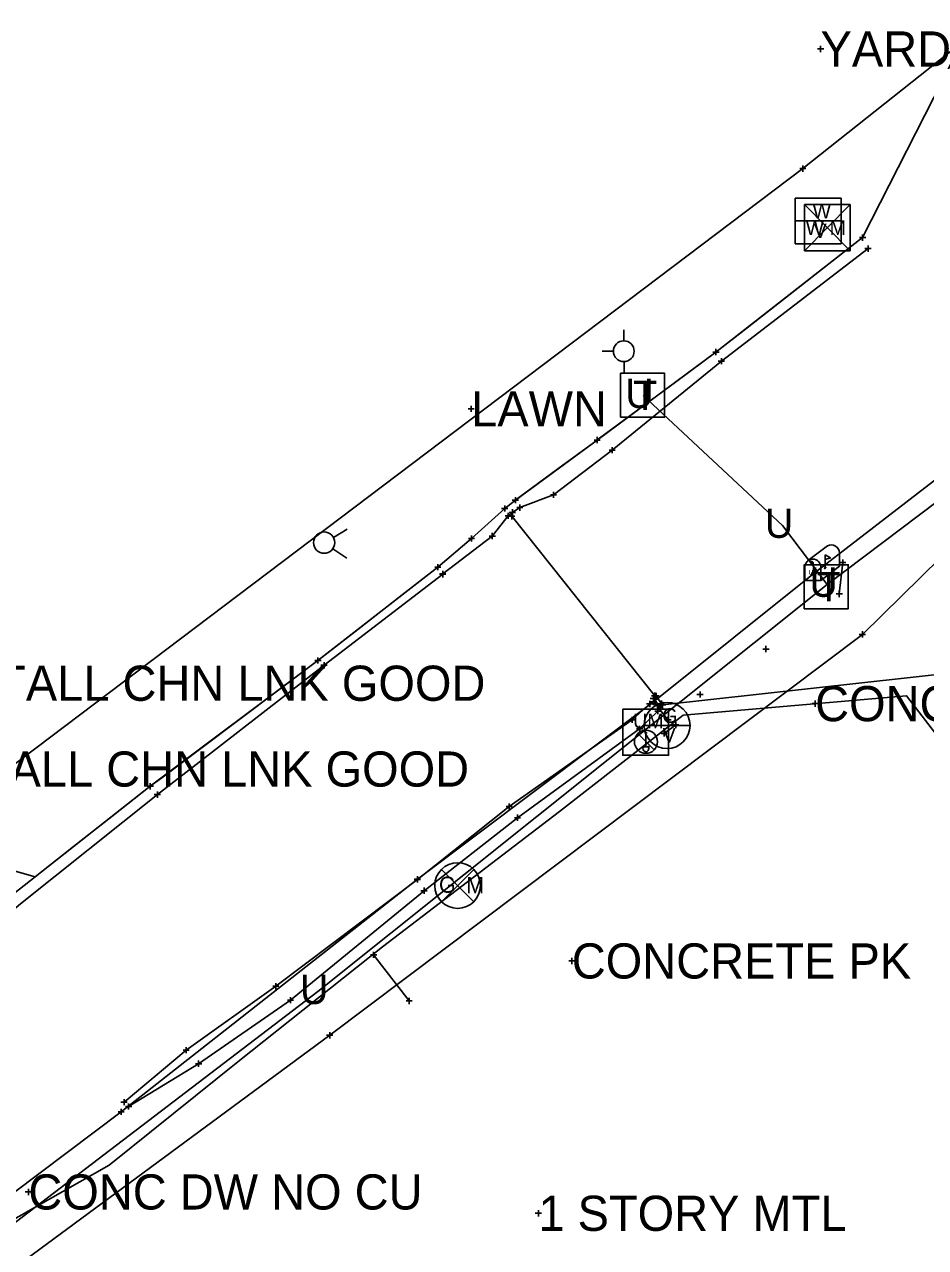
# Model space of a CAD drawing. Extents: x -1 to 1157254, y -1 to 2021979.
# Drawn here: x 1147974.3 to 1148159, y 2017757.2 to 2018007.6 of the extents above; entities that cross this region are included whole.
import ezdxf

# ---------------------------------------------------------------- set-up
doc = ezdxf.new("R2010")
doc.units = 0
for name, color, linetype in [('S_BUILDING_ANNOT', 7, 'Continuous'), ('S_CAL_CORNER', 7, 'Continuous'), ('S_CAL_CORNER_ANNOT', 7, 'Continuous'), ('S_CATCH_BASIN', 7, 'Continuous'), ('S_CATCH_BASIN_ANNOT', 7, 'Continuous'), ('S_CONTOUR_ANNOT', 7, 'Continuous'), ('S_CONTOUR_MAJOR', 7, 'Continuous'), ('S_CROSS_DRAIN', 7, 'Continuous'), ('S_DRIVEWAY_ANNOT', 7, 'Continuous'), ('S_DROP_INLET', 7, 'Continuous'), ('S_DROP_INLET_ANNOT', 7, 'Continuous'), ('S_DTM_PAVEMENT', 7, 'Continuous'), ('S_EXIST_ROW', 7, 'Continuous'), ('S_EXISTING_ALIGNMENT', 7, 'Continuous'), ('S_FENCE', 7, 'Continuous'), ('S_GAS_PUMP_ISLAND_ANNOT', 7, 'Continuous'), ('S_GATE', 7, 'Continuous')]:
    doc.layers.add(name, color=color, linetype=linetype)

msp = doc.modelspace()

# ---------------------------------------------------------------- linework, layer by layer
at = {"layer": 'S_BUILDING_ANNOT'}
for p, q in [((1148136.82, 2018002.62), (1148138.09, 2018002.62)), ((1148137.45, 2018001.99), (1148137.45, 2018003.26)), ((1148137.45, 2018002.62), (1148137.45, 2018002.62)), ((1148133.18, 2017978.12), (1148134.45, 2017978.13)), ((1148133.82, 2017977.49), (1148133.81, 2017978.76)), ((1148133.82, 2017978.13), (1148133.82, 2017978.13)), ((1148146.07, 2017963.35), (1148146.07, 2017964.62)), ((1148145.43, 2017963.99), (1148146.7, 2017963.99)), ((1148146.07, 2017963.99), (1148146.07, 2017963.99)), ((1148147.19, 2017961.09), (1148147.18, 2017962.36)), ((1148146.55, 2017961.73), (1148147.82, 2017961.73)), ((1148147.19, 2017961.73), (1148147.19, 2017961.73)), ((1148115.37, 2017940.55), (1148116.64, 2017940.55)), ((1148116.01, 2017939.91), (1148116, 2017941.19)), ((1148116, 2017940.55), (1148116, 2017940.55)), ((1148116.5, 2017938.7), (1148117.78, 2017938.7)), ((1148117.14, 2017938.06), (1148117.14, 2017939.33)), ((1148117.14, 2017938.7), (1148117.14, 2017938.7)), ((1148065.86, 2017928.3), (1148065.86, 2017929.57)), ((1148065.23, 2017928.93), (1148066.5, 2017928.94)), ((1148065.86, 2017928.93), (1148065.86, 2017928.93)), ((1148091.03, 2017922.54), (1148092.3, 2017922.54)), ((1148091.67, 2017921.9), (1148091.67, 2017923.18)), ((1148091.67, 2017922.54), (1148091.67, 2017922.54)), ((1148094.11, 2017920.47), (1148095.38, 2017920.47)), ((1148094.75, 2017919.83), (1148094.75, 2017921.11)), ((1148094.75, 2017920.47), (1148094.75, 2017920.47)), ((1148082.72, 2017910.68), (1148082.71, 2017911.95)), ((1148074.28, 2017910.22), (1148075.55, 2017910.23)), ((1148074.92, 2017909.59), (1148074.91, 2017910.86)), ((1148074.92, 2017910.22), (1148074.92, 2017910.22)), ((1148075.83, 2017908.07), (1148075.83, 2017909.34)), ((1148082.08, 2017911.31), (1148083.35, 2017911.32)), ((1148082.72, 2017911.31), (1148082.72, 2017911.31)), ((1148072.1, 2017908.52), (1148073.37, 2017908.53)), ((1148072.73, 2017907.89), (1148072.73, 2017909.16)), ((1148072.73, 2017908.52), (1148072.73, 2017908.52)), ((1148072.84, 2017907.01), (1148074.11, 2017907.01)), ((1148073.47, 2017906.37), (1148073.47, 2017907.64)), ((1148073.47, 2017907.01), (1148073.47, 2017907.01)), ((1148073.53, 2017906.94), (1148074.8, 2017906.94)), ((1148073.67, 2017907.71), (1148074.94, 2017907.71)), ((1148074.17, 2017906.3), (1148074.16, 2017907.58)), ((1148074.17, 2017906.94), (1148074.17, 2017906.94)), ((1148074.31, 2017907.07), (1148074.31, 2017908.35)), ((1148074.31, 2017907.71), (1148074.31, 2017907.71)), ((1148075.19, 2017908.7), (1148076.47, 2017908.71)), ((1148075.83, 2017908.7), (1148075.83, 2017908.7)), ((1148065.3, 2017902.36), (1148066.57, 2017902.36)), ((1148065.94, 2017901.73), (1148065.93, 2017903)), ((1148065.94, 2017902.36), (1148065.94, 2017902.36)), ((1148069.55, 2017902.87), (1148070.82, 2017902.87)), ((1148070.19, 2017902.24), (1148070.19, 2017903.51)), ((1148070.19, 2017902.87), (1148070.19, 2017902.87)), ((1148059.01, 2017895.88), (1148059.01, 2017897.15)), ((1148141.36, 2017897.47), (1148142.63, 2017897.47)), ((1148142, 2017896.84), (1148142, 2017898.11)), ((1148142, 2017897.47), (1148142, 2017897.47)), ((1148058.38, 2017896.51), (1148059.65, 2017896.51)), ((1148059.01, 2017896.51), (1148059.01, 2017896.51)), ((1148059.4, 2017895.04), (1148060.67, 2017895.04)), ((1148059.42, 2017895.15), (1148060.69, 2017895.15)), ((1148060.04, 2017894.41), (1148060.03, 2017895.68)), ((1148060.04, 2017895.04), (1148060.04, 2017895.04)), ((1148060.05, 2017894.51), (1148060.05, 2017895.78)), ((1148060.05, 2017895.15), (1148060.05, 2017895.15)), ((1148135.5, 2017895.28), (1148136.77, 2017895.28)), ((1148136.14, 2017894.65), (1148136.13, 2017895.92)), ((1148136.14, 2017895.28), (1148136.14, 2017895.28)), ((1148140.66, 2017891.02), (1148141.93, 2017891.02)), ((1148141.29, 2017890.38), (1148141.29, 2017891.66)), ((1148141.29, 2017891.02), (1148141.29, 2017891.02)), ((1148145.39, 2017882.73), (1148146.67, 2017882.74)), ((1148146.03, 2017882.1), (1148146.03, 2017883.37)), ((1148146.03, 2017882.74), (1148146.03, 2017882.74)), ((1148125.62, 2017879.74), (1148126.9, 2017879.74)), ((1148126.26, 2017879.11), (1148126.26, 2017880.38)), ((1148126.26, 2017879.74), (1148126.26, 2017879.74)), ((1148033.82, 2017877.39), (1148035.09, 2017877.4)), ((1148034.45, 2017876.76), (1148034.45, 2017878.03)), ((1148034.45, 2017877.4), (1148034.45, 2017877.4)), ((1148035.71, 2017875.77), (1148035.71, 2017877.04)), ((1148035.08, 2017876.41), (1148036.35, 2017876.41)), ((1148035.71, 2017876.41), (1148035.71, 2017876.41)), ((1148102.56, 2017869.58), (1148103.83, 2017869.58)), ((1148102.84, 2017870.19), (1148104.12, 2017870.19)), ((1148103.12, 2017870.13), (1148104.4, 2017870.13)), ((1148103.19, 2017868.95), (1148103.19, 2017870.22)), ((1148103.19, 2017869.58), (1148103.19, 2017869.58)), ((1148103.22, 2017868.32), (1148103.22, 2017869.59)), ((1148103.28, 2017868.26), (1148103.28, 2017869.53)), ((1148103.48, 2017869.56), (1148103.48, 2017870.83)), ((1148103.48, 2017870.19), (1148103.48, 2017870.19)), ((1148103.76, 2017869.5), (1148103.76, 2017870.77)), ((1148103.76, 2017870.13), (1148103.76, 2017870.13)), ((1148112.13, 2017870.42), (1148113.4, 2017870.42)), ((1148112.77, 2017869.79), (1148112.76, 2017871.06)), ((1148112.76, 2017870.42), (1148112.76, 2017870.42)), ((1148101.8, 2017868.5), (1148103.07, 2017868.5)), ((1148102.44, 2017867.87), (1148102.44, 2017869.14)), ((1148102.44, 2017868.5), (1148102.44, 2017868.5)), ((1148102.58, 2017868.95), (1148103.85, 2017868.95)), ((1148102.64, 2017868.9), (1148103.91, 2017868.9)), ((1148103.22, 2017868.95), (1148103.22, 2017868.95)), ((1148103.28, 2017868.9), (1148103.28, 2017868.9)), ((1148103.47, 2017867.04), (1148104.75, 2017867.05)), ((1148103.91, 2017867.82), (1148105.19, 2017867.83)), ((1148104.11, 2017866.41), (1148104.11, 2017867.68)), ((1148104.11, 2017867.05), (1148104.11, 2017867.05)), ((1148104.21, 2017868.54), (1148105.48, 2017868.54)), ((1148104.45, 2017868.29), (1148105.73, 2017868.3)), ((1148104.55, 2017867.19), (1148104.55, 2017868.46)), ((1148104.55, 2017867.83), (1148104.55, 2017867.83)), ((1148104.85, 2017867.91), (1148104.84, 2017869.18)), ((1148104.85, 2017868.54), (1148104.85, 2017868.54)), ((1148105.09, 2017867.66), (1148105.09, 2017868.93)), ((1148105.09, 2017868.3), (1148105.09, 2017868.3)), ((1148135.7, 2017868.56), (1148136.97, 2017868.56)), ((1148136.33, 2017867.92), (1148136.33, 2017869.2)), ((1148136.33, 2017868.56), (1148136.33, 2017868.56)), ((1148098.24, 2017865.24), (1148099.51, 2017865.24)), ((1148098.88, 2017864.61), (1148098.87, 2017865.88)), ((1148098.87, 2017865.24), (1148098.87, 2017865.24)), ((1148105.53, 2017865.23), (1148106.81, 2017865.23)), ((1148106.17, 2017864.6), (1148106.17, 2017865.87)), ((1148106.17, 2017865.23), (1148106.17, 2017865.23)), ((1148107.78, 2017863.57), (1148107.78, 2017864.84)), ((1148099.75, 2017863.39), (1148101.02, 2017863.39)), ((1148100.39, 2017862.75), (1148100.38, 2017864.03)), ((1148100.38, 2017863.39), (1148100.38, 2017863.39)), ((1148104.76, 2017862.45), (1148106.03, 2017862.46)), ((1148105.4, 2017861.82), (1148105.4, 2017863.09)), ((1148105.4, 2017862.46), (1148105.4, 2017862.46)), ((1148107.14, 2017864.2), (1148108.41, 2017864.21)), ((1148107.78, 2017864.2), (1148107.78, 2017864.2)), ((1148000.11, 2017851), (1148000.11, 2017852.27)), ((1147999.48, 2017851.64), (1148000.75, 2017851.64)), ((1148000.11, 2017851.64), (1148000.11, 2017851.64)), ((1148000.92, 2017849.93), (1148002.19, 2017849.93)), ((1148001.56, 2017849.29), (1148001.56, 2017850.57)), ((1148001.56, 2017849.93), (1148001.56, 2017849.93)), ((1148073.01, 2017847.51), (1148074.28, 2017847.51)), ((1148073.64, 2017846.87), (1148073.64, 2017848.14)), ((1148073.64, 2017847.51), (1148073.64, 2017847.51)), ((1148074.71, 2017845.2), (1148075.99, 2017845.2)), ((1148075.35, 2017844.56), (1148075.35, 2017845.83)), ((1148075.35, 2017845.2), (1148075.35, 2017845.2)), ((1148054.2, 2017832.57), (1148055.48, 2017832.57)), ((1148054.22, 2017832.59), (1148055.5, 2017832.59)), ((1148054.84, 2017831.93), (1148054.84, 2017833.21)), ((1148054.84, 2017832.57), (1148054.84, 2017832.57)), ((1148054.86, 2017831.96), (1148054.86, 2017833.23)), ((1148054.86, 2017832.59), (1148054.86, 2017832.59)), ((1148055.57, 2017830.24), (1148056.85, 2017830.25)), ((1148056.21, 2017829.61), (1148056.21, 2017830.88)), ((1148056.21, 2017830.24), (1148056.21, 2017830.24)), ((1148045.23, 2017817.12), (1148046.51, 2017817.12)), ((1148045.87, 2017816.49), (1148045.87, 2017817.76)), ((1148045.87, 2017817.12), (1148045.87, 2017817.12)), ((1148085.84, 2017815.87), (1148087.11, 2017815.87)), ((1148086.47, 2017815.23), (1148086.47, 2017816.5)), ((1148086.47, 2017815.87), (1148086.47, 2017815.87)), ((1148025.2, 2017810.69), (1148026.47, 2017810.69)), ((1148025.84, 2017810.05), (1148025.83, 2017811.33)), ((1148025.83, 2017810.69), (1148025.83, 2017810.69)), ((1148028.2, 2017807.84), (1148029.47, 2017807.85)), ((1148028.84, 2017807.21), (1148028.84, 2017808.48)), ((1148028.84, 2017807.85), (1148028.84, 2017807.85)), ((1148052.53, 2017807.69), (1148053.8, 2017807.69)), ((1148053.16, 2017807.05), (1148053.16, 2017808.32)), ((1148053.16, 2017807.69), (1148053.16, 2017807.69)), ((1148036.24, 2017800.65), (1148037.51, 2017800.66)), ((1148036.88, 2017800.02), (1148036.88, 2017801.29)), ((1148036.88, 2017800.65), (1148036.88, 2017800.65)), ((1148006.81, 2017797.6), (1148008.09, 2017797.6)), ((1148007.45, 2017796.96), (1148007.45, 2017798.24)), ((1148007.45, 2017797.6), (1148007.45, 2017797.6)), ((1148009.37, 2017794.82), (1148010.64, 2017794.83)), ((1148010, 2017794.19), (1148010, 2017795.46)), ((1148010, 2017794.83), (1148010, 2017794.83)), ((1147994.08, 2017786.96), (1147995.35, 2017786.97)), ((1147994.72, 2017786.33), (1147994.72, 2017787.6)), ((1147994.72, 2017786.97), (1147994.72, 2017786.97)), ((1147995.66, 2017785.42), (1147995.65, 2017786.7)), ((1147993.5, 2017784.96), (1147994.77, 2017784.97)), ((1147994.13, 2017784.33), (1147994.13, 2017785.6)), ((1147994.13, 2017784.96), (1147994.13, 2017784.96)), ((1147995.02, 2017786.06), (1147996.29, 2017786.06)), ((1147995.65, 2017786.06), (1147995.65, 2017786.06)), ((1147975.12, 2017767.94), (1147975.12, 2017769.21)), ((1147974.48, 2017768.57), (1147975.76, 2017768.58)), ((1147975.12, 2017768.57), (1147975.12, 2017768.57)), ((1148079, 2017764.2), (1148080.27, 2017764.2)), ((1148079.63, 2017763.57), (1148079.63, 2017764.84)), ((1148079.63, 2017764.2), (1148079.63, 2017764.2))]:
    msp.add_line(p, q, dxfattribs=at)
at = {"layer": 'S_CAL_CORNER'}
for p, q in [((1148100, 2017862.42), (1148103.33, 2017859.09)), ((1148101.51, 2017862.65), (1148101.82, 2017862.65)), ((1148101.67, 2017860.75), (1148101.67, 2017862.49)), ((1148101.07, 2017859.85), (1148101.07, 2017859.67)), ((1148101.67, 2017860.75), (1148101.67, 2017859.7)), ((1148102.26, 2017859.86), (1148102.27, 2017859.63))]:
    msp.add_line(p, q, dxfattribs=at)
msp.add_lwpolyline([(1148096.9, 2017867.41), (1148106.31, 2017867.41), (1148106.31, 2017858), (1148096.9, 2017858)], close=True, dxfattribs=at)
msp.add_circle((1148101.67, 2017860.75), 2.36, dxfattribs=at)
for centre, radius, start, end in [((1148101.67, 2017862.65), 0.156, 180, 0), ((1148101.49, 2017860.25), 0.58, 223.1344, 287.472), ((1148101.84, 2017860.25), 0.58, 252.528, 316.8656)]:
    msp.add_arc(centre, radius, start, end, dxfattribs=at)
msp.add_ellipse((1148101.67, 2017859.51), major_axis=(0, -0.82), ratio=0.744362, start_param=4.519801, end_param=8.000179, dxfattribs=at)
at = {"layer": 'S_CAL_CORNER_ANNOT'}
for p, q in [((1148101.27, 2017864.09), (1148110.72, 2017864.09)), ((1148059.77, 2017828), (1148066.39, 2017834.62)), ((1148059.77, 2017834.62), (1148066.39, 2017828))]:
    msp.add_line(p, q, dxfattribs=at)
for points in [[(1148176.11, 2017926.04), (1148136.14, 2017895.28), (1148103.22, 2017868.95), (1148054.86, 2017832.59), (1147994.13, 2017784.96), (1147955.31, 2017755.81), (1147823.06, 2017654.27), (1147729.59, 2017581.35), (1147643.02, 2017515.61), (1147594.54, 2017475.05), (1147501.21, 2017388.35), (1147435.29, 2017328.79), (1147395.53, 2017293.46), (1147348.75, 2017254.13), (1147258.66, 2017171.57), (1147166.99, 2017089.79), (1147151.24, 2017076.13), (1147027.41, 2016982.56), (1146975.56, 2016939.41), (1146851.18, 2016835.15), (1146821.23, 2016867.05), (1146788.36, 2016903.2)], [(1148103.28, 2017868.9), (1148106.17, 2017865.23)]]:
    msp.add_lwpolyline(points, dxfattribs=at)
for centre, radius in [((1148106, 2017864.09), 4.71), ((1148063.08, 2017831.31), 4.68)]:
    msp.add_circle(centre, radius, dxfattribs=at)
at = {"layer": 'S_CATCH_BASIN'}
for p, q in [((1148097.13, 2017942.84), (1148097.13, 2017945.09)), ((1148095.04, 2017940.71), (1148092.71, 2017940.71)), ((1148097.21, 2017936.29), (1148097.21, 2017938.62))]:
    msp.add_line(p, q, dxfattribs=at)
msp.add_circle((1148097.13, 2017940.73), 2.13, dxfattribs=at)
at = {"layer": 'S_CATCH_BASIN_ANNOT'}
for points in [[(1148096.48, 2017927.2), (1148096.48, 2017936.2), (1148105.48, 2017936.2), (1148105.48, 2017927.2)], [(1148134.11, 2017888), (1148134.11, 2017897), (1148143.11, 2017897), (1148143.11, 2017888)]]:
    msp.add_lwpolyline(points, close=True, dxfattribs=at)
at = {"layer": 'S_CONTOUR_ANNOT'}
for p, q in [((1148132.26, 2017972.1), (1148141.67, 2017972.1)), ((1148132.26, 2017962.69), (1148132.26, 2017972.1)), ((1148141.67, 2017972.1), (1148141.67, 2017962.69)), ((1148134.19, 2017970.77), (1148143.53, 2017970.77)), ((1148134.19, 2017970.77), (1148134.19, 2017961.28)), ((1148134.19, 2017970.77), (1148143.53, 2017961.28)), ((1148143.53, 2017970.77), (1148134.19, 2017961.28)), ((1148143.53, 2017970.77), (1148143.53, 2017961.28)), ((1148132.26, 2017967.41), (1148141.67, 2017967.41)), ((1148141.67, 2017962.69), (1148132.26, 2017962.69)), ((1148134.19, 2017961.28), (1148143.53, 2017961.28)), ((1148037.63, 2017902.59), (1148040.45, 2017904.32)), ((1148037.51, 2017900.28), (1148040.41, 2017898.36))]:
    msp.add_line(p, q, dxfattribs=at)
msp.add_lwpolyline([(1148171.01, 2018007.64), (1148133.82, 2017978.13), (1147884.86, 2017790.18), (1147810.34, 2017733.24), (1147725.21, 2017658.34), (1147638.36, 2017588.8), (1147507.67, 2017474.52), (1147125.41, 2017140.99), (1145970.62, 2016384.06)], dxfattribs=at)
msp.add_circle((1148035.73, 2017901.54), 2.18, dxfattribs=at)
at = {"layer": 'S_CROSS_DRAIN'}
for p, q in [((1148134.76, 2017897.77), (1148138.89, 2017900.88)), ((1148141.32, 2017899.41), (1148141.32, 2017896.69)), ((1148138.37, 2017899.06), (1148138.37, 2017896.35)), ((1148134.21, 2017896.5), (1148134.21, 2017893.78)), ((1148137.53, 2017893.78), (1148141.32, 2017896.69)), ((1148137.53, 2017896.5), (1148137.53, 2017893.78)), ((1148134.21, 2017893.78), (1148137.53, 2017893.78))]:
    msp.add_line(p, q, dxfattribs=at)
for points in [[(1148135.39, 2017897.61), (1148135.61, 2017897.47), (1148135.61, 2017897.09), (1148135.92, 2017897.09), (1148135.92, 2017897.45), (1148135.72, 2017897.7), (1148135.39, 2017897.64)], [(1148138.37, 2017899.06), (1148139.48, 2017898.39), (1148138.37, 2017898.05)]]:
    msp.add_lwpolyline(points, dxfattribs=at)
for centre, end in [((1148139.66, 2017899.41), 117.5718), ((1148135.87, 2017896.5), 180)]:
    msp.add_arc(centre, 1.66, 0, end, dxfattribs=at)
msp.add_ellipse((1148138.37, 2017896.35), major_axis=(0.145, 0.132), ratio=0.564646, dxfattribs=at)
at = {"layer": 'S_DRIVEWAY_ANNOT'}
for points in [[(1148146.07, 2017963.99), (1148116, 2017940.55), (1148091.67, 2017922.54), (1148074.92, 2017910.22), (1148072.73, 2017908.52), (1148065.94, 2017902.36), (1148059.01, 2017896.51), (1148034.45, 2017877.4), (1148000.11, 2017851.64), (1147972.03, 2017829.56), (1147962.17, 2017823.16), (1147961.53, 2017820.07)], [(1148147.19, 2017961.73), (1148117.14, 2017938.7), (1148094.75, 2017920.47), (1148082.72, 2017911.31), (1148075.83, 2017908.7), (1148074.31, 2017907.71), (1148073.47, 2017907.01), (1148070.19, 2017902.87), (1148060.05, 2017895.15), (1148060.04, 2017895.04), (1148035.71, 2017876.41), (1148001.56, 2017849.93), (1147973.52, 2017827.54), (1147965.98, 2017821.25), (1147961.96, 2017819.65)], [(1148104.55, 2017867.83), (1148103.19, 2017869.58), (1148103.76, 2017870.13), (1148104.85, 2017868.54)], [(1148102.44, 2017868.5), (1148098.87, 2017865.24), (1148073.64, 2017847.51), (1148054.84, 2017832.57), (1148025.83, 2017810.69), (1148007.45, 2017797.6), (1147994.72, 2017786.97)], [(1148104.11, 2017867.05), (1148100.38, 2017863.39), (1148075.35, 2017845.2), (1148056.21, 2017830.24), (1148028.84, 2017807.85), (1148010, 2017794.83), (1147995.65, 2017786.06)]]:
    msp.add_lwpolyline(points, dxfattribs=at)
at = {"layer": 'S_DROP_INLET'}
for points in [[(1148195.53, 2017935.77), (1148138.82, 2017892.99), (1148034.43, 2017809.59), (1147909.47, 2017714.32), (1147828.88, 2017654.71), (1147681.29, 2017538.62), (1147545.03, 2017424.01), (1147436.65, 2017326.84), (1147356.29, 2017257.74), (1147237.67, 2017148.84), (1147152.37, 2017082.27), (1147079.41, 2017020.24), (1146950.46, 2016911.58), (1146849.38, 2016826.65), (1146763.18, 2016745.2), (1146663.11, 2016665.75), (1146626.02, 2016634.68), (1146520.54, 2016557.46), (1146484.38, 2016531.03)], [(1148138.81, 2017892.97), (1148129.68, 2017905.05), (1148101.09, 2017931.63)]]:
    msp.add_lwpolyline(points, dxfattribs=at)
at = {"layer": 'S_DROP_INLET_ANNOT'}
msp.add_lwpolyline([(1148105.09, 2017868.3), (1148165.71, 2017874.98)], dxfattribs=at)
at = {"layer": 'S_DTM_PAVEMENT'}
msp.add_lwpolyline([(1148045.87, 2017817.12), (1148053.16, 2017807.69)], dxfattribs=at)
at = {"layer": 'S_EXIST_ROW'}
msp.add_lwpolyline([(1148074.17, 2017906.94), (1148103.48, 2017870.19)], dxfattribs=at)
at = {"layer": 'S_EXISTING_ALIGNMENT'}
for points in [[(1148141.29, 2017891.02), (1148142, 2017897.47)], [(1148107.78, 2017864.2), (1148105.4, 2017862.46)]]:
    msp.add_lwpolyline(points, dxfattribs=at)
at = {"layer": 'S_FENCE'}
msp.add_lwpolyline([(1148182.05, 2017918.06), (1148146.03, 2017882.74), (1148036.88, 2017800.65), (1147915.13, 2017710.9), (1147841.97, 2017653.39), (1147689.75, 2017529.1), (1147550.85, 2017419.33), (1147452.64, 2017321.35), (1147370.71, 2017243.52), (1147258.33, 2017138.3), (1147166.15, 2017078.02), (1147070.18, 2016992.83), (1146962.81, 2016905.87), (1146854.86, 2016827.91), (1146747.33, 2016742.81), (1146665.82, 2016680.99), (1146623.06, 2016638.6), (1146514.26, 2016556.71), (1146391.39, 2016471.4), (1146322.08, 2016427.51), (1146235.84, 2016374), (1146176.66, 2016335.01), (1146181.42, 2016326.5)], dxfattribs=at)
at = {"layer": 'S_GAS_PUMP_ISLAND_ANNOT'}
for points in [[(1148167.87, 2018006.85), (1148146.07, 2017963.99), (1148138.18, 2017957.84), (1148130.29, 2017951.69), (1148122.41, 2017945.54), (1148116, 2017940.55), (1148107.97, 2017934.6), (1148099.93, 2017928.65), (1148091.89, 2017922.71), (1148091.67, 2017922.54), (1148083.61, 2017916.62), (1148075.56, 2017910.69), (1148074.92, 2017910.22), (1148072.73, 2017908.52), (1148065.94, 2017902.36), (1148059.01, 2017896.51), (1148051.12, 2017890.37), (1148043.23, 2017884.23), (1148035.34, 2017878.09), (1148034.45, 2017877.4), (1148026.45, 2017871.4), (1148018.45, 2017865.4), (1148010.45, 2017859.39), (1148002.45, 2017853.39), (1148000.11, 2017851.64), (1147992.25, 2017845.46), (1147984.39, 2017839.28), (1147976.53, 2017833.1), (1147930.34, 2017846.21)], [(1147864.93, 2017602.24), (1147872.24, 2017609.07), (1147876.8, 2017613.19), (1147884.21, 2017619.9), (1147893.42, 2017628.14), (1147901.06, 2017634.59), (1147908.7, 2017641.04), (1147916.34, 2017647.48), (1147923.98, 2017653.93), (1147967.03, 2017678.46), (1147963.21, 2017696.53), (1147959.8, 2017712.65), (1147956.81, 2017727.08), (1147963.62, 2017758.13), (1147991.68, 2017774.07), (1148018.07, 2017795.23), (1148047.66, 2017818.79), (1148083.98, 2017846.49), (1148109.31, 2017866.17), (1148155.09, 2017870.18), (1148173.15, 2017846.7)]]:
    msp.add_lwpolyline(points, dxfattribs=at)

# ---------------------------------------------------------------- texts
at = {"layer": 'S_CAL_CORNER'}
msp.add_text('UM', height=2.999, dxfattribs=at).set_placement((1148099.04, 2017863.53))
at = {"layer": 'S_CAL_CORNER_ANNOT'}
for s, height, p in [('G', 3, (1148105.02, 2017864.62)), ('V', 3, (1148105.08, 2017860.56)), ('G', 3.3, (1148059.26, 2017829.84)), ('M', 3.3, (1148064.83, 2017829.74))]:
    msp.add_text(s, height=height, dxfattribs=at).set_placement(p)
at = {"layer": 'S_CATCH_BASIN_ANNOT'}
for p in [(1148099.05, 2017928.7), (1148136.67, 2017889.5)]:
    msp.add_text('T', height=6, dxfattribs=at).set_placement(p)
at = {"layer": 'S_CONTOUR_ANNOT'}
for s, height, p in [('W', 3, (1148135.81, 2017967.94)), ('W M', 2.999, (1148134.4, 2017964.54)), ('V', 3, (1148136.05, 2017963.88))]:
    msp.add_text(s, height=height, dxfattribs=at).set_placement(p)
at = {"layer": 'S_CONTOUR_MAJOR'}
for p in [(1148097.46, 2017929.09), (1148126.05, 2017902.5), (1148135.18, 2017890.43), (1148135.19, 2017890.45), (1148030.8, 2017807.05)]:
    msp.add_text('U', height=6, dxfattribs=at).set_placement(p)
at = {"layer": 'S_CROSS_DRAIN'}
msp.add_text('US', height=0.96, dxfattribs=at).set_placement((1148134.97, 2017894.98))
at = {"layer": 'S_GATE'}
for s, p in [('YARD', (1148137.45, 2017999.02)), ('LAWN', (1148065.86, 2017925.33)), ('4.50 TALL CHN LNK GOOD', (1147947.31, 2017869.14)), ('CONCRETE DRIVE', (1148136.33, 2017864.96)), ('4.50 TALL CHN LNK GOOD', (1147943.97, 2017851.57)), ('CONCRETE PK', (1148086.47, 2017812.27)), ('CONC DW NO CU', (1147975.12, 2017764.97)), ('1 STORY MTL', (1148079.63, 2017760.6))]:
    msp.add_text(s, height=7.2, dxfattribs=at).set_placement(p)

doc.saveas('drawing.dxf')
